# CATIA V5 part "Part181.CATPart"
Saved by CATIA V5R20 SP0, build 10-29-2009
Part number: FA 126700-3
Revision: ANY
Definition: UNKNOWN
Nomenclature: FA 126700-3
Source: Unknown
Bounding box of the stored display mesh (mm): x -3.264 to 3.264, y -2.475 to 2.475, z -3 to 3
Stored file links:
  C:\Users\Utente\Desktop\IO LAVORO\3D X SITO CF\CUMSA\3D files FA\FA 126712-20\Part181.CATPart

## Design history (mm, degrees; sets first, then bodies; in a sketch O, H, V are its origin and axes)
Body1 "Chaflán4" (main body)
  Solid1: solid without history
